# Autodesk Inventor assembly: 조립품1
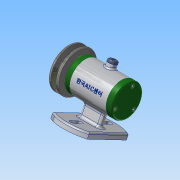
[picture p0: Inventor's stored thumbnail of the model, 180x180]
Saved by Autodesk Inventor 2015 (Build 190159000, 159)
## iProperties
Created: 2017-12
Part Number: 조립품1
Document SubType Name: Assembly
Designer: Administrator
Author: Administrator
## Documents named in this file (14)
- C:\Users\Administrator\Desktop\471208V1019\조립품1.iam
- C:\Users\Administrator\Desktop\471208V1019\부품1.ipt
- C:\Users\Administrator\Desktop\471208V1019\볼트 M4 x 12.ipt
- C:\Users\Administrator\Desktop\471208V1019\뒤커버.ipt
- C:\Users\Administrator\Desktop\471208V1019\앞커버.ipt
- C:\Users\Administrator\Desktop\471208V1019\베어링 15 x 32 x 9.ipt
- C:\Users\Administrator\Desktop\471208V1019\축.ipt
- C:\Users\Administrator\Desktop\471208V1019\오일 실 15 25 7.ipt
- C:\Users\Administrator\Desktop\471208V1019\키 3 x 3 x 12.ipt
- C:\Users\Administrator\Desktop\471208V1019\V벨트풀리.ipt
- C:\Users\Administrator\Desktop\471208V1019\와셔 8x17.ipt
- C:\Users\Administrator\Desktop\471208V1019\스프링와셔 8.ipt
- C:\Users\Administrator\Desktop\471208V1019\너트 M 8.ipt
- C:\Users\Administrator\Desktop\471208V1019\고무캡.ipt
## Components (2 placed, 2 different names)
1. V벨트풀리:1 — 각도:2
2. 고무캡:1
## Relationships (1: Angle 1)
- 각도:2 [Angle]: V벨트풀리:1
